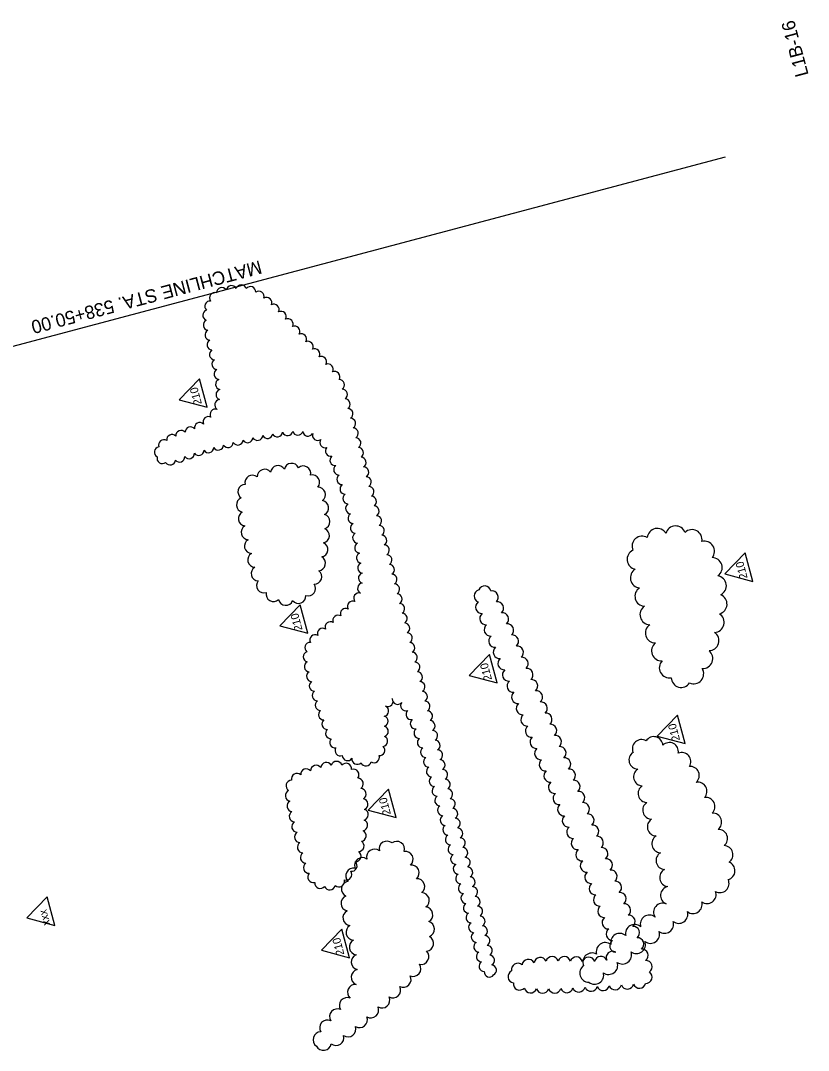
# Model space of a CAD drawing. Extents: x 930124 to 931163, y 628803 to 630086.
# Drawn here: x 930405 to 930878, y 629469 to 630086 of the extents above; entities that cross this region are included whole.
import ezdxf

# ---------------------------------------------------------------- set-up
doc = ezdxf.new("R2010")
doc.units = 0
for name, color, linetype in [('Cloud_dp', 7, 'Continuous'), ('MatchLines_dp', 7, 'Continuous'), ('TextShtNo', 7, 'Continuous')]:
    doc.layers.add(name, color=color, linetype=linetype)

msp = doc.modelspace()

# ---------------------------------------------------------------- linework, layer by layer
at = {"layer": 'Cloud_dp'}
for points in [[(930500.36, 629859), (930517.12, 629854.54), (930512.58, 629871.6)], [(930827.55, 629754.51), (930844.31, 629750.05), (930839.77, 629767.11)], [(930560.71, 629723.42), (930577.47, 629718.96), (930572.93, 629736.02)], [(930674.33, 629693.58), (930691.08, 629689.12), (930686.55, 629706.18)], [(930787.06, 629657.28), (930803.81, 629652.82), (930799.28, 629669.88)], [(930613.7, 629612.9), (930630.46, 629608.44), (930625.93, 629625.5)], [(930409.11, 629548.17), (930425.87, 629543.7), (930421.33, 629560.76)], [(930585.8, 629528.79), (930602.56, 629524.33), (930598.02, 629541.38)]]:
    msp.add_lwpolyline(points, close=True, dxfattribs=at)
for centre, radius, start, end in [((930526, 629923.09), 3.17, 34.19789, 179.19789), ((930531.75, 629924.31), 3.17, 24.86638, 169.86638), ((930537.66, 629924.73), 3.17, 18.13244, 163.13244), ((930543.14, 629923.72), 3.17, 356.09836, 141.09836), ((930518.93, 629915.07), 3.17, 83.3311, 228.3311), ((930521.84, 629920.12), 3.17, 71.7294, 216.7294), ((930548.18, 629920.95), 3.17, 341.33098, 126.33098), ((930552.82, 629917.22), 3.17, 336.04276, 121.04276), ((930517.71, 629909.66), 3.17, 106.34844, 251.34844), ((930557.22, 629913.13), 3.17, 333.15057, 118.15057), ((930518.06, 629903.79), 3.17, 115.4284, 260.4284), ((930561.45, 629908.86), 3.17, 331.26962, 116.26962), ((930565.57, 629904.46), 3.17, 329.92393, 114.92393), ((930519.06, 629897.89), 3.17, 118.76609, 263.76609), ((930569.6, 629899.97), 3.17, 328.93736, 113.93736), ((930520.33, 629892), 3.17, 120.63884, 265.63884), ((930573.59, 629895.43), 3.17, 328.74445, 113.74445), ((930577.58, 629890.88), 3.17, 328.80876, 113.80876), ((930521.76, 629886.15), 3.17, 121.87707, 266.87707), ((930581.58, 629886.34), 3.17, 328.89987, 113.89987), ((930523.23, 629880.27), 3.17, 121.2063, 266.2063), ((930585.59, 629881.81), 3.17, 329.04404, 114.04404), ((930524.52, 629874.31), 3.17, 118.13014, 263.13014), ((930589.62, 629877.29), 3.17, 329.32988, 114.32988), ((930593.6, 629872.76), 3.17, 328.43218, 113.43218), ((930525.41, 629868.26), 3.17, 113.6771, 258.6771), ((930596.33, 629867.93), 3.17, 305.49726, 90.49726), ((930525.69, 629862.11), 3.17, 106.57379, 251.57379), ((930598.11, 629862.17), 3.17, 303.77074, 88.77074), ((930524.89, 629855.93), 3.17, 93.57999, 238.57999), ((930599.78, 629856.37), 3.17, 303.27874, 88.27874), ((930522.11, 629850.26), 3.17, 69.15693, 214.15693), ((930601.41, 629850.55), 3.17, 303.01378, 88.01378), ((930512.81, 629842.13), 3.17, 46.30923, 191.30923), ((930517.88, 629845.74), 3.17, 59.67077, 204.67077), ((930603.01, 629844.72), 3.17, 302.84144, 87.84144), ((930496.11, 629834.96), 3.17, 43.23339, 188.23339), ((930501.58, 629837.42), 3.17, 40.08304, 185.08304), ((930507.18, 629839.59), 3.17, 37.28018, 182.28018), ((930553.34, 629838.96), 3.17, 208.19902, 353.19902), ((930559.34, 629839.97), 3.17, 206.05257, 351.05257), ((930565.4, 629840.71), 3.17, 202.86434, 347.86434), ((930571.52, 629841), 3.17, 197.4456, 342.4456), ((930577.7, 629840.34), 3.17, 185.44163, 330.44163), ((930583.47, 629837.76), 3.17, 161.37647, 306.37647), ((930604.61, 629838.89), 3.17, 302.71777, 87.71777), ((930491.24, 629831.86), 3.17, 56.81517, 201.81517), ((930523.85, 629831.99), 3.17, 212.37389, 357.37389), ((930529.71, 629833.51), 3.17, 211.77083, 356.77083), ((930535.59, 629834.98), 3.17, 211.30096, 356.30096), ((930541.47, 629836.4), 3.17, 210.85305, 355.85305), ((930547.39, 629837.75), 3.17, 209.76535, 354.76535), ((930587.94, 629833.39), 3.17, 144.9038, 289.9038), ((930606.19, 629833.05), 3.17, 302.62343, 87.62343), ((930488.72, 629827.53), 3.17, 97.67952, 242.67952), ((930506.38, 629826.82), 3.17, 216.34522, 1.34522), ((930512.17, 629828.69), 3.17, 214.37392, 359.37392), ((930518, 629830.39), 3.17, 213.18787, 358.18787), ((930591.31, 629828.21), 3.17, 136.12536, 281.12536), ((930607.76, 629827.21), 3.17, 302.54839, 87.54839), ((930490.31, 629823.83), 3.17, 163.79807, 308.79807), ((930495, 629823.02), 3.17, 211.47429, 356.47429), ((930500.66, 629824.77), 3.17, 218.03013, 3.03013), ((930559.64, 629815.08), 4.45, 30.10292, 175.10292), ((930567.84, 629816.42), 4.45, 23.36161, 168.36161), ((930593.99, 629822.69), 3.17, 130.81201, 275.81201), ((930596.23, 629817.01), 3.17, 127.24991, 272.24991), ((930609.33, 629821.37), 3.17, 302.48685, 87.48685), ((930544.3, 629809.32), 4.44, 49.22213, 194.22213), ((930551.64, 629812.81), 4.45, 36.6434, 181.6434), ((930574.84, 629814.82), 4.45, 345.8973, 130.8973), ((930580.21, 629809.42), 4.45, 318.84952, 103.84952), ((930598.2, 629811.26), 3.17, 125.4887, 270.4887), ((930610.89, 629815.53), 3.17, 302.43518, 87.43518), ((930540.08, 629803.78), 4.45, 91.17954, 236.17954), ((930600.02, 629805.48), 3.17, 124.44084, 269.44084), ((930612.45, 629809.68), 3.17, 302.39101, 87.39101), ((930583.68, 629802.05), 4.45, 306.52469, 91.52469), ((930601.73, 629799.66), 3.17, 123.41791, 268.41791), ((930614, 629803.83), 3.17, 302.35267, 87.35267), ((930615.55, 629797.99), 3.17, 302.31899, 87.31899), ((930539.26, 629795.95), 4.45, 111.83627, 256.83627), ((930585.64, 629794.08), 4.45, 296.11279, 81.11279), ((930603.35, 629793.81), 3.17, 122.41988, 267.41988), ((930617.1, 629792.14), 3.17, 302.28909, 87.28909), ((930540.33, 629787.7), 4.45, 117.8996, 262.8996), ((930586.32, 629785.83), 4.45, 288.3734, 73.3734), ((930604.86, 629787.94), 3.17, 121.44662, 266.44662), ((930618.64, 629786.29), 3.17, 302.26231, 87.26231), ((930542.05, 629779.46), 4.45, 120.74031, 265.74031), ((930606.27, 629782.04), 3.17, 120.49794, 265.49794), ((930620.18, 629780.44), 3.17, 302.23815, 87.23815), ((930798.07, 629777.28), 6.01, 20.40716, 165.40716), ((930586.05, 629777.49), 4.45, 282.87996, 67.87996), ((930607.59, 629776.12), 3.17, 119.57356, 264.57356), ((930621.72, 629774.59), 3.17, 302.21621, 87.21621), ((930777.95, 629771.17), 6.01, 59.0373, 204.0373), ((930787.04, 629775.79), 6.02, 29.92904, 174.92904), ((930807.92, 629775.09), 6.01, 349.51329, 134.51329), ((930544.01, 629771.22), 4.45, 121.05118, 266.05118), ((930585.14, 629769.14), 4.45, 279.63354, 64.63354), ((930608.8, 629770.18), 3.17, 118.48787, 263.48787), ((930623.25, 629768.74), 3.17, 302.19616, 87.19616), ((930815.34, 629768.17), 6.01, 319.56154, 104.56154), ((930546, 629762.97), 4.45, 121.05118, 266.05118), ((930583.69, 629760.89), 4.45, 275.42503, 60.42503), ((930609.86, 629764.19), 3.17, 116.55846, 261.55846), ((930624.79, 629762.89), 3.17, 302.17775, 87.17775), ((930774.96, 629763.25), 6.01, 114.51601, 259.51601), ((930819.95, 629758.26), 6.01, 305.30325, 90.30325), ((930548.03, 629754.76), 4.44, 121.74399, 266.74399), ((930610.67, 629758.15), 3.17, 113.64537, 258.64537), ((930626.32, 629757.04), 3.17, 302.16077, 87.16077), ((930581.46, 629752.89), 4.45, 268.498, 53.498), ((930611.06, 629752.03), 3.17, 108.66408, 253.66408), ((930627.85, 629751.19), 3.17, 302.14503, 87.14503), ((930776.94, 629752.17), 6.01, 120.70494, 265.70494), ((930822.46, 629747.42), 6.01, 295.76047, 80.76047), ((930551.31, 629747.62), 4.45, 142.60594, 287.60594), ((930577.76, 629745.81), 4.45, 251.3574, 36.3574), ((930610.57, 629745.84), 3.17, 97.30771, 242.30771), ((930629.38, 629745.33), 3.17, 302.1304, 87.1304), ((930683.6, 629743.47), 3.82, 12.13101, 157.13101), ((930779.7, 629741.09), 6.01, 122.29679, 267.29679), ((930557, 629742.42), 4.45, 167.46108, 312.46108), ((930564.33, 629740.14), 4.45, 193.07403, 338.07403), ((930571.91, 629741.28), 4.45, 219.04888, 4.04888), ((930608.25, 629739.98), 3.17, 74.61014, 219.61014), ((930630.9, 629739.48), 3.17, 302.11676, 87.11676), ((930681.07, 629741.26), 3.82, 104.8427, 249.8427), ((930687.95, 629740.5), 3.82, 314.35153, 99.35153), ((930822.88, 629736.41), 6.01, 283.56574, 68.56574), ((930600.24, 629730.67), 3.17, 61.03595, 206.03595), ((930604.5, 629735.07), 3.17, 65.66595, 210.66595), ((930632.43, 629733.63), 3.17, 302.10398, 87.10398), ((930681.98, 629734.58), 3.82, 125.67294, 270.67294), ((930691.12, 629733.99), 3.82, 312.54257, 97.54257), ((930782.7, 629730.05), 6.01, 123.14977, 268.14977), ((930595.72, 629726.59), 3.17, 58.21863, 203.21863), ((930633.95, 629727.77), 3.17, 302.092, 87.092), ((930684.43, 629727.8), 3.82, 129.06831, 274.06831), ((930694.16, 629727.39), 3.82, 311.83999, 96.83999), ((930821.12, 629725.45), 6.01, 273.21736, 58.21736), ((930586.47, 629718.77), 3.17, 57.34358, 202.34358), ((930591.11, 629722.66), 3.17, 57.62802, 202.62802), ((930635.48, 629721.92), 3.17, 302.08072, 87.08072), ((930687.12, 629721.04), 3.82, 129.3905, 274.3905), ((930697.13, 629720.75), 3.82, 311.43507, 96.43507), ((930785.94, 629719.11), 6.01, 124.75487, 269.75487), ((930581.95, 629714.81), 3.17, 60.06251, 205.06251), ((930637, 629716.07), 3.17, 302.07009, 87.07009), ((930689.84, 629714.29), 3.82, 129.515, 274.515), ((930700.07, 629714.09), 3.82, 311.163, 96.163), ((930818.05, 629714.5), 6.01, 270.42346, 55.42346), ((930578.93, 629710.3), 3.17, 87.29601, 232.29601), ((930638.52, 629710.21), 3.17, 302.06004, 87.06004), ((930692.57, 629707.54), 3.82, 129.58668, 274.58668), ((930702.98, 629707.42), 3.82, 310.96394, 95.96394), ((930789.63, 629708.36), 6.01, 128.1325, 273.1325), ((930814.37, 629703.76), 6.01, 266.76633, 51.76633), ((930578, 629704.79), 3.17, 108.51333, 253.51333), ((930640.04, 629704.36), 3.17, 302.05051, 87.05051), ((930695.31, 629700.8), 3.82, 129.63483, 274.63483), ((930705.87, 629700.74), 3.82, 310.81012, 95.81012), ((930794.28, 629698.18), 6.01, 135.96426, 280.96426), ((930578.62, 629698.96), 3.17, 118.75099, 263.75099), ((930641.56, 629698.5), 3.17, 302.04148, 87.04148), ((930698.06, 629694.05), 3.82, 129.67005, 274.67005), ((930708.74, 629694.05), 3.82, 310.68662, 95.68662), ((930808.88, 629694.65), 6.01, 246.11528, 31.11528), ((930579.96, 629693.13), 3.17, 122.11395, 267.11395), ((930581.57, 629687.33), 3.17, 123.91277, 268.91277), ((930643.08, 629692.65), 3.17, 302.0331, 87.0331), ((930644.6, 629686.79), 3.17, 302.02624, 87.02624), ((930700.81, 629687.31), 3.82, 129.69726, 274.69726), ((930711.6, 629687.36), 3.82, 310.58464, 95.58464), ((930801.43, 629692.45), 6.01, 181.71148, 326.71148), ((930583.33, 629681.56), 3.17, 125.07389, 270.07389), ((930646.11, 629680.93), 3.17, 302.01931, 87.01931), ((930703.56, 629680.57), 3.82, 129.71911, 274.71911), ((930714.45, 629680.66), 3.82, 310.49856, 95.49856), ((930585.19, 629675.82), 3.17, 125.79902, 270.79902), ((930625.49, 629678.05), 3.17, 246.1361, 31.1361), ((930631.37, 629679.45), 3.17, 175.63091, 320.63091), ((930636.37, 629675.56), 3.17, 143.57686, 288.57686), ((930647.63, 629675.08), 3.17, 302.012, 87.012), ((930717.29, 629673.96), 3.82, 310.42464, 95.42464), ((930587.13, 629670.1), 3.17, 126.55437, 271.55437), ((930622.86, 629672.28), 3.17, 279.87258, 64.87258), ((930639.6, 629670.29), 3.17, 134.51856, 279.51856), ((930649.14, 629669.22), 3.17, 302.00428, 87.00428), ((930706.31, 629673.83), 3.82, 129.73715, 274.73715), ((930589.15, 629664.42), 3.17, 127.68793, 272.68793), ((930622.55, 629666.1), 3.17, 289.35817, 74.35817), ((930642.17, 629664.74), 3.17, 130.15908, 275.15908), ((930650.66, 629663.37), 3.17, 301.99611, 86.99611), ((930709.07, 629667.09), 3.82, 129.75238, 274.75238), ((930720.12, 629667.25), 3.82, 310.36026, 95.36026), ((930591.33, 629658.81), 3.17, 129.68415, 274.68415), ((930622.65, 629660.08), 3.17, 287.63031, 72.63031), ((930644.39, 629659.06), 3.17, 127.52826, 272.52826), ((930652.17, 629657.51), 3.17, 301.98745, 86.98745), ((930711.83, 629660.35), 3.82, 129.76546, 274.76546), ((930722.95, 629660.54), 3.82, 310.30352, 95.30352), ((930593.82, 629653.4), 3.17, 134.69315, 279.69315), ((930622.23, 629654.21), 3.17, 279.2065, 64.2065), ((930646.4, 629653.33), 3.17, 125.99789, 270.99789), ((930653.69, 629651.65), 3.17, 301.97824, 86.97824), ((930714.59, 629653.62), 3.82, 129.77685, 274.77685), ((930725.76, 629653.83), 3.82, 310.25304, 95.25304), ((930777.57, 629649.68), 5.45, 59.22565, 204.22565), ((930784.97, 629651.46), 5.45, 2.83286, 147.83286), ((930794.29, 629647.91), 5.45, 350.53791, 135.53791), ((930597.02, 629648.56), 3.17, 147.34507, 292.34507), ((930620.63, 629648.71), 3.17, 263.13676, 48.13676), ((930648.27, 629647.56), 3.17, 125.09269, 270.09269), ((930655.2, 629645.8), 3.17, 301.96842, 86.96842), ((930717.35, 629646.88), 3.82, 129.78688, 274.78688), ((930728.58, 629647.12), 3.82, 310.20773, 95.20773), ((930775.54, 629642.86), 5.45, 122.66736, 267.66736), ((930801.73, 629641.98), 5.45, 327.29247, 112.29247), ((930588.66, 629638.03), 3.36, 29.80654, 174.80654), ((930594.79, 629638.73), 3.36, 18.32748, 163.32748), ((930600.5, 629637.57), 3.36, 353.6605, 138.6605), ((930601.4, 629645.68), 3.17, 181.01569, 326.01569), ((930607.16, 629643.46), 3.17, 171.84194, 316.84194), ((930612.41, 629642.5), 3.17, 202.45882, 347.45882), ((930617.28, 629644.44), 3.17, 235.86517, 20.86517), ((930650.07, 629641.78), 3.17, 124.47859, 269.47859), ((930656.71, 629639.94), 3.17, 301.95792, 86.95792), ((930720.11, 629640.14), 3.82, 129.79582, 274.79582), ((930731.39, 629640.4), 3.82, 310.16676, 95.16676), ((930571.02, 629631.49), 3.36, 47.54088, 192.54088), ((930576.63, 629634.22), 3.36, 39.28387, 184.28387), ((930582.59, 629636.38), 3.36, 35.59343, 180.59343), ((930604.87, 629634.01), 3.36, 322.90615, 107.90615), ((930651.82, 629635.98), 3.17, 124.02675, 269.02675), ((930658.22, 629634.08), 3.17, 301.94666, 86.94666), ((930722.87, 629633.41), 3.82, 129.80383, 274.80383), ((930734.19, 629633.68), 3.82, 310.1295, 95.1295), ((930778.28, 629632.84), 5.45, 122.85863, 267.85863), ((930806.82, 629633.61), 5.45, 310.35936, 95.35936), ((930567.85, 629627.41), 3.35, 91.96082, 236.96082), ((930607.46, 629628.63), 3.36, 303.57672, 88.57672), ((930653.52, 629630.17), 3.17, 123.6763, 268.6763), ((930659.73, 629628.22), 3.17, 301.93454, 86.93454), ((930725.64, 629626.67), 3.82, 129.80137, 274.80137), ((930736.99, 629626.96), 3.82, 310.09404, 95.09404), ((930811.42, 629624.12), 5.45, 316.34057, 101.34057), ((930567.42, 629621.54), 3.36, 114.54564, 259.54564), ((930609.17, 629622.47), 3.36, 302.39045, 87.39045), ((930655.2, 629624.35), 3.17, 123.39423, 268.39423), ((930661.23, 629622.37), 3.17, 301.92145, 86.92145), ((930728.4, 629619.93), 3.82, 129.74282, 274.74282), ((930739.78, 629620.24), 3.82, 310.05128, 95.05128), ((930781.03, 629622.83), 5.45, 122.90915, 267.90915), ((930568.42, 629615.3), 3.36, 118.76501, 263.76501), ((930610.29, 629616.35), 3.36, 293.367, 78.367), ((930656.84, 629618.53), 3.17, 123.16084, 268.16084), ((930662.74, 629616.51), 3.17, 301.90726, 86.90726), ((930731.15, 629613.19), 3.82, 129.6688, 274.6688), ((930742.57, 629613.51), 3.82, 310.00341, 95.00341), ((930783.79, 629612.82), 5.45, 122.93644, 267.93644), ((930816.19, 629614.98), 5.45, 313.80903, 98.80903), ((930569.78, 629609.07), 3.36, 120.83179, 265.83179), ((930610.43, 629610.13), 3.36, 284.28947, 69.28947), ((930658.47, 629612.7), 3.17, 122.96356, 267.96356), ((930660.07, 629606.86), 3.17, 122.79395, 267.79395), ((930664.24, 629610.65), 3.17, 301.89178, 86.89178), ((930733.89, 629606.44), 3.82, 129.5855, 274.5855), ((930745.36, 629606.79), 3.82, 309.95062, 94.95062), ((930820.19, 629605.61), 5.45, 307.32882, 92.32882), ((930571.32, 629602.88), 3.36, 122.09954, 267.09954), ((930609.99, 629603.77), 3.36, 282.63544, 67.63544), ((930661.66, 629601.02), 3.17, 122.6461, 267.6461), ((930665.75, 629604.79), 3.17, 301.87484, 86.87484), ((930748.13, 629600.06), 3.82, 309.89204, 94.89204), ((930786.55, 629602.79), 5.45, 122.79425, 267.79425), ((930572.96, 629596.7), 3.36, 122.66401, 267.66401), ((930609.19, 629597.5), 3.36, 277.94467, 62.94467), ((930663.23, 629595.18), 3.17, 122.51571, 267.51571), ((930667.25, 629598.93), 3.17, 301.85616, 86.85616), ((930736.63, 629599.69), 3.82, 129.49082, 274.49082), ((930750.9, 629593.32), 3.82, 309.82649, 94.82649), ((930789.24, 629592.74), 5.45, 122.14308, 267.14308), ((930823.75, 629595.84), 5.45, 307.74986, 92.74986), ((930574.66, 629590.54), 3.36, 123.16899, 268.16899), ((930607.89, 629591.32), 3.36, 273.21956, 58.21956), ((930624.98, 629589.55), 4.69, 49.52611, 194.52611), ((930630.91, 629589.42), 4.69, 342.95324, 127.95324), ((930664.8, 629589.33), 3.17, 122.3996, 267.3996), ((930668.75, 629593.07), 3.17, 301.83543, 86.83543), ((930739.35, 629592.93), 3.82, 129.38188, 274.38188), ((930827.01, 629586.09), 5.45, 304.20941, 89.20941), ((930576.43, 629584.4), 3.36, 123.99813, 268.99813), ((930606.08, 629585.27), 3.36, 268.5265, 53.5265), ((930617.46, 629584.76), 4.69, 50.51454, 195.51454), ((930635.97, 629583.4), 4.69, 312.02489, 97.02489), ((930666.35, 629583.48), 3.17, 122.29534, 267.29534), ((930670.24, 629587.21), 3.17, 301.81226, 86.81226), ((930742.05, 629586.17), 3.82, 129.25471, 274.25471), ((930753.66, 629586.59), 3.82, 309.7525, 94.7525), ((930791.77, 629582.63), 5.45, 121.01798, 266.01798), ((930578.34, 629578.32), 3.36, 125.80069, 270.80069), ((930603.71, 629579.45), 3.36, 262.23649, 47.23649), ((930610.25, 629579.66), 4.69, 55.04243, 200.04243), ((930639.61, 629575.25), 4.69, 311.09846, 96.09846), ((930667.89, 629577.63), 3.17, 122.20968, 267.20968), ((930671.74, 629581.35), 3.17, 301.78612, 86.78612), ((930673.23, 629575.48), 3.17, 301.75631, 86.75631), ((930744.74, 629579.4), 3.82, 129.10357, 274.10357), ((930756.41, 629579.85), 3.82, 309.66806, 94.66806), ((930828.18, 629576.48), 5.45, 284.65198, 69.65198), ((930580.9, 629572.74), 3.36, 138.60744, 283.60744), ((930600.54, 629574.15), 3.36, 250.89996, 35.89996), ((930605, 629573.44), 4.69, 79.56161, 224.56161), ((930669.42, 629571.78), 3.17, 122.20632, 267.20632), ((930674.71, 629569.62), 3.17, 301.72189, 86.72189), ((930747.42, 629572.63), 3.82, 128.91985, 273.91985), ((930759.16, 629573.1), 3.82, 309.57047, 94.57047), ((930793.98, 629572.41), 5.45, 118.35059, 263.35059), ((930585.04, 629569.23), 3.36, 175.73057, 320.73057), ((930590.76, 629568.34), 3.36, 201.59719, 346.59719), ((930596.2, 629570.12), 3.36, 229.80865, 14.80865), ((930602.45, 629565.53), 4.69, 99.68112, 244.68112), ((930642.93, 629567.03), 4.69, 307.89845, 92.89845), ((930670.96, 629565.93), 3.17, 122.22338, 267.22338), ((930676.2, 629563.76), 3.17, 301.68153, 86.68153), ((930750.06, 629565.84), 3.82, 128.68983, 273.68983), ((930761.88, 629566.36), 3.82, 309.4559, 94.4559), ((930794.48, 629561.67), 5.45, 102.03645, 247.03645), ((930824.66, 629568.82), 5.45, 240.9735, 25.9735), ((930602.15, 629556.92), 4.69, 111.38989, 256.38989), ((930645.71, 629558.64), 4.69, 303.80999, 88.80999), ((930672.5, 629560.08), 3.17, 122.24354, 267.24354), ((930677.68, 629557.89), 3.17, 301.63329, 86.63329), ((930752.68, 629559.04), 3.82, 128.39002, 273.39002), ((930764.6, 629559.6), 3.82, 309.3188, 94.3188), ((930816.88, 629562.25), 5.45, 234.364, 19.364), ((930647.79, 629550.09), 4.69, 298.53864, 83.53864), ((930674.04, 629554.23), 3.17, 122.26785, 267.26785), ((930679.15, 629552.03), 3.17, 301.57422, 86.57422), ((930755.25, 629552.22), 3.82, 127.9759, 272.9759), ((930767.29, 629552.84), 3.82, 309.15061, 94.15061), ((930790.3, 629551.62), 5.45, 67.73279, 212.73279), ((930808.5, 629556.23), 5.45, 232.09103, 17.09103), ((930603.28, 629548.24), 4.69, 118.4465, 263.4465), ((930675.58, 629548.38), 3.17, 122.29799, 267.29799), ((930680.62, 629546.16), 3.17, 301.49954, 86.49954), ((930757.77, 629545.37), 3.82, 127.34875, 272.34875), ((930769.96, 629546.07), 3.82, 308.93748, 93.93748), ((930782.32, 629544.41), 5.45, 51.49134, 196.49134), ((930799.94, 629550.34), 5.45, 231.94162, 16.94162), ((930605.19, 629539.58), 4.69, 121.40717, 266.40717), ((930648.82, 629541.43), 4.69, 290.09456, 75.09456), ((930677.13, 629542.54), 3.17, 122.33675, 267.33675), ((930682.08, 629540.29), 3.17, 301.40085, 86.40085), ((930760.18, 629538.48), 3.82, 126.22175, 271.22175), ((930773.48, 629538.8), 5.45, 48.25496, 193.25496), ((930772.61, 629539.3), 3.82, 308.65489, 93.65489), ((930791.39, 629544.41), 5.45, 232.61224, 17.61224), ((930648.23, 629532.89), 4.69, 276.89986, 61.89986), ((930678.68, 629536.69), 3.17, 122.3892, 267.3892), ((930683.52, 629534.42), 3.17, 301.26162, 86.26162), ((930764.56, 629533.47), 5.45, 48.46497, 193.46497), ((930775.21, 629532.5), 3.82, 308.25425, 93.25425), ((930782.92, 629538.37), 5.45, 233.31771, 18.31771), ((930607.09, 629530.75), 4.69, 117.87601, 262.87601), ((930680.24, 629530.85), 3.17, 122.46607, 267.46607), ((930684.95, 629528.55), 3.17, 301.04297, 86.04297), ((930755.89, 629527.93), 5.45, 51.77142, 196.77142), ((930762.34, 629531.45), 3.82, 122.90591, 267.90591), ((930774.52, 629532.22), 5.45, 234.06084, 19.06084), ((930777.75, 629525.69), 3.82, 307.61962, 92.61962), ((930608.27, 629521.76), 4.69, 112.09023, 257.09023), ((930645.44, 629524.95), 4.69, 259.43668, 44.43668), ((930681.81, 629525.01), 3.17, 122.59549, 267.59549), ((930686.34, 629522.67), 3.17, 300.61707, 85.61707), ((930709.81, 629519.52), 3.82, 27.99463, 172.99463), ((930716.94, 629520.64), 3.82, 24.73024, 169.73024), ((930724.07, 629521.16), 3.82, 18.64364, 163.64364), ((930731.3, 629521.14), 3.82, 16.04244, 161.04244), ((930738.57, 629520.95), 3.82, 16.04244, 161.04244), ((930745.89, 629520.87), 3.82, 17.68805, 162.68805), ((930747.85, 629521.7), 5.45, 58.67069, 203.67069), ((930753.27, 629521.27), 3.82, 23.52716, 168.52716), ((930760.24, 629524.36), 3.81, 59.22549, 204.22549), ((930766.2, 629525.96), 5.45, 234.83798, 19.83798), ((930608.24, 629512.61), 4.69, 102.50122, 247.50122), ((930640.65, 629517.79), 4.69, 247.92991, 32.92991), ((930683.4, 629519.18), 3.17, 122.8982, 267.8982), ((930687.51, 629516.79), 3.18, 296.9147, 81.9147), ((930703.44, 629517.18), 3.82, 47.35778, 192.35778), ((930746, 629515.07), 5.44, 125.24951, 270.24951), ((930757.91, 629519.72), 5.45, 234.14847, 19.14847), ((930780.17, 629518.85), 3.82, 306.35924, 91.35924), ((930634.77, 629511.2), 4.69, 243.66845, 28.66845), ((930686.44, 629515.87), 3.16, 177.59681, 322.59681), ((930701.37, 629512.93), 3.82, 115.88486, 260.88486), ((930749.48, 629513.84), 5.45, 230.62789, 15.62789), ((930780.17, 629512.7), 3.82, 268.71131, 53.71131), ((930606.02, 629503.6), 4.69, 84.85289, 229.85289), ((930628.49, 629504.91), 4.69, 241.39844, 26.39844), ((930704.56, 629508.68), 3.82, 172.73526, 317.73526), ((930711.09, 629507.03), 3.82, 193.90077, 338.90077), ((930718.29, 629506.79), 3.82, 197.36429, 342.36429), ((930725.54, 629506.88), 3.82, 199.0598, 344.0598), ((930732.79, 629507.15), 3.82, 200.11544, 345.11544), ((930740.05, 629507.53), 3.82, 200.84195, 345.84195), ((930747.31, 629507.96), 3.82, 201.04812, 346.04812), ((930754.58, 629508.42), 3.82, 201.06518, 346.06518), ((930761.85, 629508.87), 3.82, 201.09018, 346.09018), ((930769.11, 629509.33), 3.82, 201.13233, 346.13233), ((930776.38, 629509.8), 3.82, 201.23132, 346.23132), ((930601.18, 629495.7), 4.69, 67.09764, 212.09764), ((930621.99, 629498.82), 4.69, 239.93594, 24.93594), ((930595.29, 629488.92), 4.69, 65.98401, 210.98401), ((930615.35, 629492.86), 4.69, 238.87969, 23.87969), ((930589.35, 629482.23), 4.69, 65.77213, 210.77213), ((930608.6, 629487.04), 4.69, 237.59437, 22.59437), ((930585.36, 629475.14), 4.69, 90.50757, 235.50757), ((930601.69, 629481.45), 4.69, 235.42599, 20.42599), ((930594.51, 629476.34), 4.69, 230.39416, 15.39416), ((930586.88, 629473.39), 4.69, 206.88166, 351.88166)]:
    msp.add_arc(centre, radius, start, end, dxfattribs=at)
at = {"layer": 'MatchLines_dp'}
msp.add_lwpolyline([(930827.71, 630004.46), (930472.01, 629909.88), (930124.1, 629817.37)], dxfattribs=at)

# ---------------------------------------------------------------- texts
at = {"layer": 'Cloud_dp'}
for s, p in [('210', (930514.08, 629856.59)), ('210', (930841.27, 629752.1)), ('210', (930574.43, 629721.01)), ('210', (930688.05, 629691.17)), ('210', (930800.78, 629654.87)), ('210', (930627.42, 629610.49)), ('xxx', (930423.22, 629544.29)), ('210', (930599.52, 629526.37))]:
    msp.add_text(s, height=4.799, rotation=104.89046, dxfattribs=at).set_placement(p)
at = {"layer": 'MatchLines_dp'}
msp.add_text('MATCHLINE STA. 538+50.00', height=8, rotation=194.89045, dxfattribs=at).set_placement((930548.67, 629942.68))
at = {"layer": 'TextShtNo'}
msp.add_text('L1B-16', height=8, rotation=104.89045, dxfattribs=at).set_placement((930877.89, 630053.89))

doc.saveas('drawing.dxf')
